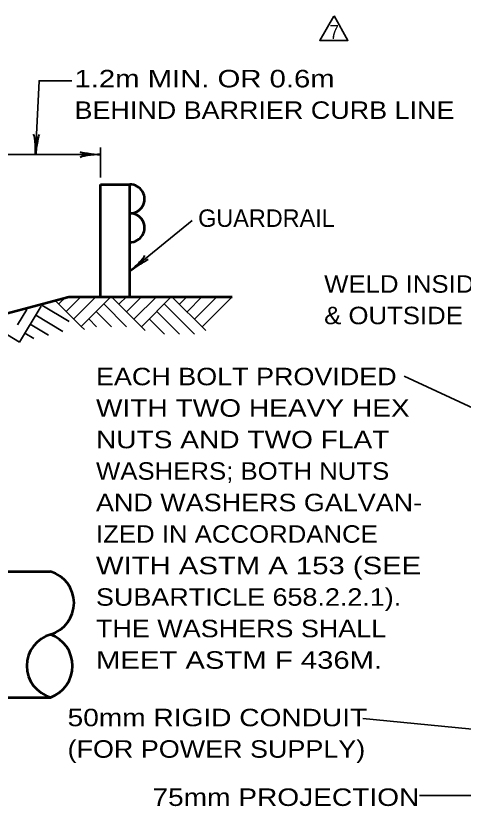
# Model space of a CAD drawing. Extents: x -39 to 816, y -16 to 528.
# Drawn here: x 157 to 233.6, y 210.1 to 345.6 of the extents above; entities that cross this region are included whole.
import ezdxf

# ---------------------------------------------------------------- set-up
doc = ezdxf.new("R2010")
doc.units = 0
doc.header["$LTSCALE"] = 0.97
doc.layers.add('1', color=7, linetype='Continuous', lineweight=35)

msp = doc.modelspace()

# ---------------------------------------------------------------- linework, layer by layer
at = {"layer": '1'}
for p, q in [((171.4654, 317.8543), (171.4654, 322.9916)), ((149.2334, 321.7916), (171.4654, 321.7916)), ((176.6709, 301.9077), (187.1869, 310.4635)), ((165.6246, 297.4648), (164.3286, 296.1688)), ((168.1686, 297.4648), (165.6006, 294.8968)), ((170.7366, 297.4648), (166.8966, 293.6008)), ((173.3046, 297.4648), (168.1686, 292.3288)), ((179.1366, 291.6328), (173.3046, 297.4648)), ((175.9926, 297.4648), (174.6966, 296.1688)), ((178.5606, 297.4648), (175.9926, 294.8968)), ((181.1286, 297.4648), (177.2646, 293.6008)), ((183.6726, 297.4648), (178.5606, 292.3288)), ((189.5286, 291.6328), (183.6726, 297.4648)), ((186.3606, 297.4648), (185.0166, 296.1208)), ((188.9286, 297.4648), (186.3126, 294.8248)), ((191.4966, 297.4648), (187.5846, 293.5528)), ((194.0166, 297.3928), (188.8806, 292.2568)), ((161.333, 295.8179), (157.5801, 289.6189)), ((166.0863, 293.1498), (161.4474, 295.9731)), ((175.9206, 292.2568), (172.0326, 296.1688)), ((187.5846, 290.9848), (182.4006, 296.1688)), ((158.8378, 295.2107), (157.273, 292.607)), ((165.0424, 291.4346), (160.4035, 294.2579)), ((173.3526, 292.2568), (170.7366, 294.8968)), ((185.0166, 290.9848), (181.1286, 294.8968)), ((157.5801, 289.6189), (151.3755, 293.3951)), ((162.5472, 290.8275), (159.4449, 292.7155)), ((170.8086, 292.2568), (169.4646, 293.6008)), ((182.4726, 290.9848), (179.8326, 293.6008)), ((160.0754, 290.226), (158.5154, 291.1556)), ((260.7254, 266.3956), (223.5246, 283.8137)), ((237.4509, 223.0514), (216.4342, 225.0824))]:
    msp.add_line(p, q, dxfattribs=at)
at = {"layer": '1', "lineweight": 53}
for p, q in [((171.4654, 297.3833), (171.4654, 316.6543)), ((171.4654, 316.6543), (176.5349, 316.6543)), ((176.5349, 297.3833), (176.5349, 316.6543)), ((66.9097, 250.3246), (162.9097, 250.3246)), ((66.9097, 228.7246), (162.9097, 228.7246))]:
    msp.add_line(p, q, dxfattribs=at)
at = {"layer": '1'}
for points in [[(211.4685, 345.5147), (209.0685, 341.3578), (213.8685, 341.3578), (211.5023, 345.5732)], [(160.3494, 321.7916), (160.9669, 334.4368), (166.5755, 334.4368)], [(168.7206, 291.7768), (168.1686, 292.3288), (163.7221, 296.7753)], [(245.8934, 220.7236), (241.0934, 211.9156), (226.1338, 211.9156)]]:
    msp.add_lwpolyline(points, dxfattribs=at)
at = {"layer": '1', "lineweight": 53}
msp.add_lwpolyline([(149.2334, 292.9425), (166.0562, 297.3928), (194.0166, 297.3928)], dxfattribs=at)
for centre, radius, start, end in [((176.5628, 314.183), 2.4714, 269.2778, 90.64679), ((176.5595, 309.2404), 2.4714, 269.2778, 90.64679), ((161.3092, 244.9246), 5.6322, 286.50947, 73.49053), ((164.4279, 234.1246), 5.5897, 104.96917, 255.03083), ((160.9405, 234.1246), 5.7478, 290.03515, 69.96485)]:
    msp.add_arc(centre, radius, start, end, dxfattribs=at)
at = {"layer": '1', "lineweight": 40}
for centre, major_axis, ratio, start_param, end_param in [((160.0821, 323.1157), (0.0826, -2.1494), 0.122415, 0.89635335, 3.14159265), ((160.6686, 323.1222), (-0.3133, -2.095), 0.07063, 3.14071475, 5.41810995), ((170.156, 321.46), (2.1428, 0.1874), 0.122415, 0.89635335, 3.14159265), ((170.156, 321.46), (2.1428, 0.1874), 0.122415, 0.89635335, 3.14159265), ((170.1208, 322.0455), (2.1077, -0.2108), 0.07063, 3.14071475, 5.41810995), ((170.1208, 322.0455), (2.1077, -0.2108), 0.07063, 3.14071475, 5.41810995), ((177.4774, 302.9913), (-1.5439, -1.4977), 0.122415, 0.89635335, 3.14159265), ((177.8742, 302.5593), (-1.768, -1.1667), 0.07063, 3.14071475, 5.41810995)]:
    msp.add_ellipse(centre, major_axis=major_axis, ratio=ratio, start_param=start_param, end_param=end_param, dxfattribs=at)

# ---------------------------------------------------------------- texts
at = {"layer": '1'}
for s, height, width, p in [('7', 2.4, 0.9, (210.7338, 341.624)), ('1.2m MIN. OR 0.6m', 3, 1.25, (167.023, 333.303)), ('BEHIND BARRIER CURB LINE', 3, 1.15, (167.023, 327.903)), ('WELD INSIDE', 3, 1.1, (209.8066, 298.0978)), ('& OUTSIDE', 3, 1.1, (209.8066, 292.6978)), ('EACH BOLT PROVIDED', 3, 1.15, (170.7074, 282.2332)), ('WITH TWO HEAVY HEX', 3, 1.2, (170.7074, 276.8332)), ('NUTS AND TWO FLAT', 3, 1.2, (170.7074, 271.4332)), ('WASHERS; BOTH NUTS', 3, 1.1, (170.7074, 266.0332)), ('AND WASHERS GALVAN-', 3, 1.15, (170.7074, 260.6332)), ('IZED IN ACCORDANCE', 3, 1.1, (170.7074, 255.2332)), ('WITH ASTM A 153 (SEE', 3, 1.25, (170.7074, 249.8332)), ('SUBARTICLE 658.2.2.1).', 3, 1.15, (170.7074, 244.4332)), ('THE WASHERS SHALL', 3, 1.15, (170.7074, 239.0332)), ('MEET ASTM F 436M.', 3, 1.25, (170.7074, 233.6332)), ('50mm RIGID CONDUIT', 3, 1.2, (165.8386, 223.7746)), ('(FOR POWER SUPPLY)', 3, 1.15, (165.8386, 218.3746)), ('75mm PROJECTION', 3, 1.2, (180.3807, 210.1128))]:
    msp.add_text(s, height=height, dxfattribs=dict(at, width=width)).set_placement(p)
msp.add_text('GUARDRAIL', height=3, dxfattribs=at).set_placement((188.2136, 309.3843))

doc.saveas('drawing.dxf')
